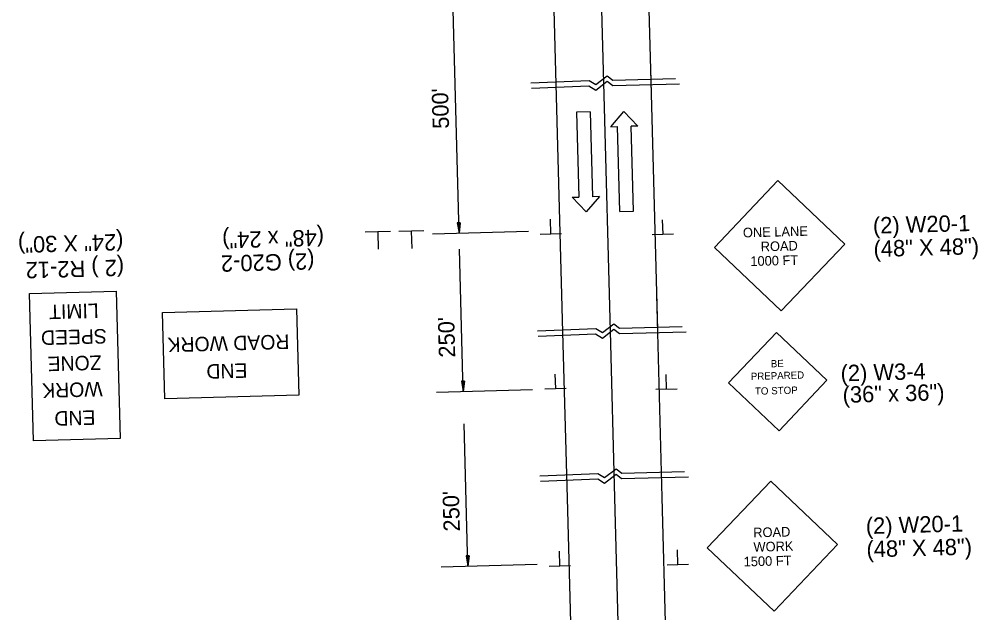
# Model space of a CAD drawing. Extents: x 1929624 to 1936506, y 596315 to 605721.
# Drawn here: x 1929624.4 to 1929984.1, y 598502.4 to 598725.3 of the extents above; entities that cross this region are included whole.
import ezdxf

# ---------------------------------------------------------------- set-up
doc = ezdxf.new("R2010")
doc.units = 0
doc.layers.add('Default', color=7, linetype='Continuous')
doc.layers.add('R_MOT', color=7, linetype='Continuous')

msp = doc.modelspace()

# ---------------------------------------------------------------- linework, layer by layer
at = {"layer": 'Default'}
for p, q in [((1929826.09, 598696.32), (1929821.7, 598859.91)), ((1929843.87, 598696.8), (1929839.48, 598860.38)), ((1929861.66, 598697.28), (1929857.27, 598860.86)), ((1929789.48, 598645), (1929786.8, 598744.72)), ((1929864.04, 598608.69), (1929861.41, 598706.66)), ((1929828.47, 598607.74), (1929826.09, 598696.32)), ((1929846.25, 598608.22), (1929843.87, 598696.8)), ((1929909.07, 598664.69), (1929885.28, 598639.58)), ((1929934.18, 598640.89), (1929909.07, 598664.69)), ((1929823.97, 598644.71), (1929823.82, 598650.18)), ((1929866.01, 598644.55), (1929865.86, 598650.01)), ((1929754.23, 598645.41), (1929763.71, 598645.67)), ((1929766.84, 598645.75), (1929776.32, 598646.01)), ((1929771.56, 598645.74), (1929771.73, 598639.26)), ((1929779.46, 598644.73), (1929815.48, 598645.7)), ((1929789.95, 598648.85), (1929788.8, 598648.82)), ((1929788.8, 598648.82), (1929789.48, 598645)), ((1929788.89, 598648.82), (1929789.46, 598645.64)), ((1929788.99, 598648.83), (1929789.44, 598646.3)), ((1929789.09, 598648.83), (1929789.42, 598646.94)), ((1929789.18, 598648.83), (1929789.41, 598647.59)), ((1929789.28, 598648.83), (1929789.39, 598648.23)), ((1929789.46, 598648.84), (1929789.39, 598648.23)), ((1929789.56, 598648.84), (1929789.41, 598647.59)), ((1929789.66, 598648.84), (1929789.42, 598646.94)), ((1929789.75, 598648.85), (1929789.44, 598646.3)), ((1929789.85, 598648.85), (1929789.46, 598645.64)), ((1929789.95, 598648.85), (1929789.48, 598645)), ((1929758.95, 598645.4), (1929759.13, 598638.93)), ((1929827.95, 598644.7), (1929819.95, 598644.49)), ((1929869.99, 598644.54), (1929861.99, 598644.32)), ((1929791.07, 598585.57), (1929789.64, 598638.95)), ((1929910.38, 598615.81), (1929885.28, 598639.58)), ((1929934.18, 598640.89), (1929910.38, 598615.81)), ((1929865.73, 598545.76), (1929863.68, 598621.81)), ((1929830.14, 598545.5), (1929828.47, 598607.74)), ((1929847.93, 598545.63), (1929846.25, 598608.22)), ((1929908.55, 598607.69), (1929890.62, 598588.73)), ((1929927.53, 598589.78), (1929908.55, 598607.69)), ((1929825.74, 598586.62), (1929825.6, 598592.08)), ((1929867.35, 598586.44), (1929867.21, 598591.9)), ((1929791.54, 598589.42), (1929790.39, 598589.39)), ((1929790.39, 598589.39), (1929791.07, 598585.57)), ((1929790.49, 598589.39), (1929791.05, 598586.21)), ((1929790.59, 598589.39), (1929791.04, 598586.87)), ((1929790.68, 598589.4), (1929791.02, 598587.51)), ((1929790.78, 598589.4), (1929791, 598588.16)), ((1929790.88, 598589.4), (1929790.98, 598588.8)), ((1929791.06, 598589.41), (1929790.98, 598588.8)), ((1929791.15, 598589.41), (1929791, 598588.16)), ((1929791.25, 598589.41), (1929791.02, 598587.51)), ((1929791.35, 598589.41), (1929791.04, 598586.87)), ((1929791.45, 598589.42), (1929791.05, 598586.21)), ((1929791.54, 598589.42), (1929791.07, 598585.57)), ((1929909.61, 598570.8), (1929890.62, 598588.73)), ((1929927.53, 598589.78), (1929909.61, 598570.8)), ((1929781.06, 598585.3), (1929817.07, 598586.27)), ((1929829.73, 598586.61), (1929821.72, 598586.39)), ((1929871.34, 598586.43), (1929863.33, 598586.21)), ((1929792.83, 598519.94), (1929791.4, 598573.32)), ((1929906.41, 598551.87), (1929882.62, 598526.76)), ((1929931.52, 598528.07), (1929906.41, 598551.87)), ((1929831.84, 598482.11), (1929830.14, 598545.5)), ((1929849.61, 598483.05), (1929847.93, 598545.63)), ((1929867.38, 598484), (1929865.73, 598545.76)), ((1929931.52, 598528.07), (1929907.73, 598502.98)), ((1929793.3, 598523.79), (1929792.15, 598523.76)), ((1929792.15, 598523.76), (1929792.83, 598519.94)), ((1929792.25, 598523.76), (1929792.82, 598520.58)), ((1929792.35, 598523.76), (1929792.8, 598521.24)), ((1929792.44, 598523.77), (1929792.78, 598521.88)), ((1929792.54, 598523.77), (1929792.76, 598522.53)), ((1929792.64, 598523.77), (1929792.75, 598523.17)), ((1929792.82, 598523.78), (1929792.75, 598523.17)), ((1929792.92, 598523.78), (1929792.76, 598522.53)), ((1929793.02, 598523.78), (1929792.78, 598521.88)), ((1929793.11, 598523.78), (1929792.8, 598521.24)), ((1929793.21, 598523.79), (1929792.82, 598520.58)), ((1929793.3, 598523.79), (1929792.83, 598519.94)), ((1929827.29, 598520.05), (1929827.14, 598525.51)), ((1929871.56, 598520.55), (1929871.41, 598526.01)), ((1929907.73, 598502.98), (1929882.62, 598526.76)), ((1929782.82, 598519.67), (1929818.83, 598520.64)), ((1929831.27, 598520.04), (1929823.27, 598519.82)), ((1929875.54, 598520.53), (1929867.54, 598520.32))]:
    msp.add_line(p, q, dxfattribs=at)
for points in [[(1929816.47, 598701.43), (1929838.26, 598702.34), (1929840.77, 598700.75), (1929845.11, 598704.11), (1929847.2, 598702.46), (1929870.7, 598703.08)], [(1929816.72, 598699.39), (1929838.23, 598700.3), (1929840.74, 598698.7), (1929845.08, 598702.06), (1929847.17, 598700.41), (1929872.19, 598701.08)], [(1929818.97, 598608.3), (1929840.76, 598609.21), (1929843.27, 598607.62), (1929847.61, 598610.97), (1929849.7, 598609.33), (1929873.2, 598609.95)], [(1929819.22, 598606.26), (1929840.73, 598607.17), (1929843.24, 598605.57), (1929847.58, 598608.93), (1929849.67, 598607.28), (1929874.69, 598607.95)], [(1929819.79, 598553.84), (1929841.57, 598554.75), (1929844.09, 598553.16), (1929848.43, 598556.52), (1929850.52, 598554.87), (1929874.01, 598555.49)], [(1929820.04, 598551.8), (1929841.54, 598552.71), (1929844.06, 598551.11), (1929848.4, 598554.47), (1929850.49, 598552.82), (1929875.51, 598553.49)]]:
    msp.add_lwpolyline(points, dxfattribs=at)
for points in [[(1929629.84, 598567.01), (1929628.36, 598622.32), (1929660.79, 598623.19), (1929662.28, 598567.88)], [(1929729.37, 598584.12), (1929679.14, 598582.77), (1929678.26, 598615.21), (1929728.5, 598616.55)]]:
    msp.add_lwpolyline(points, close=True, dxfattribs=at)
at = {"layer": 'R_MOT'}
for p, q in [((1929838.71, 598690.6), (1929833.6, 598690.47)), ((1929833.6, 598690.47), (1929834.46, 598658.53)), ((1929838.71, 598690.6), (1929839.57, 598658.67)), ((1929846.37, 598684.93), (1929851.34, 598690.68)), ((1929851.34, 598690.68), (1929856.6, 598685.21)), ((1929856.6, 598685.21), (1929854.04, 598685.14)), ((1929846.37, 598684.93), (1929848.93, 598685)), ((1929849.79, 598653.06), (1929848.93, 598685)), ((1929854.9, 598653.2), (1929854.04, 598685.14)), ((1929831.9, 598658.46), (1929834.46, 598658.53)), ((1929837.17, 598652.99), (1929831.9, 598658.46)), ((1929842.13, 598658.73), (1929837.17, 598652.99)), ((1929842.13, 598658.73), (1929839.57, 598658.67)), ((1929849.79, 598653.06), (1929854.9, 598653.2))]:
    msp.add_line(p, q, dxfattribs=at)

# ---------------------------------------------------------------- texts
at = {"layer": 'Default'}
for s, height, rotation, p in [("500'", 6.14, 91.5377, (1929785.75, 598684.24)), ('(2) W20-1', 6.14, 1.5377, (1929944.84, 598644.78)), ('(24" X 30")', 6.1396, 181.5377, (1929663.49, 598644.73)), ('(48" x 24")', 6.1396, 181.5377, (1929738.75, 598646.38)), ('ONE LANE', 3.603, 1.5381, (1929896.03, 598643.36)), ('ROAD', 3.602, 1.5377, (1929902.71, 598638.13)), ('(48" X 48")', 6.1396, 1.5377, (1929945.07, 598636.02)), ('(2) G20-2', 6.14, 181.5377, (1929735.19, 598637.53)), ('(2 ) R2-12', 6.14, 181.5377, (1929663.75, 598635.1)), ('1000 FT', 3.604, 1.5383, (1929898.82, 598632.62)), ('LIMIT', 5.443, 181.5377, (1929654.19, 598618.6)), ("250'", 6.14, 91.5377, (1929788.06, 598598.32)), ('SPEED', 5.443, 181.5377, (1929657.23, 598609.03)), ('ROAD WORK', 5.444, 181.5377, (1929725.73, 598606.94)), ('ZONE', 5.443, 181.5377, (1929655.25, 598599.1)), ('END', 5.444, 181.5377, (1929710, 598596.13)), ('BE', 2.72, 1.6381, (1929906.49, 598594.57)), ('(2) W3-4', 6.14, 1.5377, (1929932.71, 598589.3)), ('PREPARED', 2.719, 1.638, (1929898.99, 598589.82)), ('WORK ', 5.444, 181.5377, (1929655.66, 598589.15)), ('(36" x 36")', 6.1396, 1.5377, (1929933.47, 598581.23)), ('TO STOP', 2.737, 1.5383, (1929900.52, 598584.26)), ('END', 5.444, 181.5377, (1929652.97, 598578.47)), ("250'", 6.14, 91.5377, (1929789.81, 598533.01)), ('(2) W20-1', 6.14, 1.5377, (1929942.18, 598531.96)), ('ROAD', 3.603, 1.5381, (1929899.91, 598530.71)), ('(48" X 48")', 6.1396, 1.5377, (1929942.42, 598523.2)), ('WORK', 3.602, 1.5377, (1929899.99, 598525.3)), ('1500 FT', 3.604, 1.5383, (1929896.31, 598519.8))]:
    msp.add_text(s, height=height, rotation=rotation, dxfattribs=at).set_placement(p)

doc.saveas('drawing.dxf')
